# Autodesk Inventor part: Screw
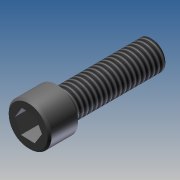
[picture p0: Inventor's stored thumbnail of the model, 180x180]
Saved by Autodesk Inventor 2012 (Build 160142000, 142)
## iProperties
Shininess: 64.0
Length Units: 11272
Angle Units: 11278
Time Units: 11290
Mass Units: 11284
Length Display Precision: 3
Angle Display Precision: 2
Compacted: True
Part Number: Screw
Document SubType Name: Modeling
Created: 2006-07
Designer: Z.MCGILL
Manufacturer: Standard
Standards Organization: Custom
Material: system_material_0
Description: SCREW, CAP, 1/4-20 X 3/8
Engineer: SAP
Density: 7.84168 g/cm^3
Mass: 26.2447 g
Surface Area: 18.9522 cm^2
Volume: 3.34682 cm^3
Density: 0.0
Volumn: 0.0
Area: 0.0
PropertySet Name: Model Information
Control State: 0
Master: False
Checked Out: False
NetWeight: 0.005
WeightUOM: KG
ModelCode: Comp
Author: Z.MCGILL
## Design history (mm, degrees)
sketch "PROTRUSION id 114-Sketch"
  geometry: L1 (0, 9.525)-(-7.144, 9.525); L2 (-7.144, 9.525)-(-7.144, 0); L3 (-7.144, 0)-(-4.763, 0); L4 (-4.763, 0)-(-4.763, -31.75); L5 (-4.763, -31.75)-(0, -31.75); L6 (0, -31.75)-(0, 9.525); L7 (0, 14.605)-(0, -27.305); L8 (0, -546.1)-(0, 3054.35) reference; L9 (0, 0)-(0, 2540); L10 (-515.143, 0)-(3049.19, 0) reference; L11 (0, 0)-(2540, 0)
  constraints: 18 end point, 2 collinear
  dimensions: "Thread_Length" = 31.75 distance between parallel lines of L3 L5; "Thread_Diameter" = 9.525 diameter of L4 L6; "Head_Diameter" = 14.2875 diameter of L2 L6; "Head_Length" = 9.525 distance between parallel lines of L1 L3
revolve "PROTRUSION id 114" sketch "PROTRUSION id 114-Sketch" stored, may be unused: angle "d6" = 0 deg
chamfer "head_chamfer" distance "Head_Chamfer" = 0.635; stored, may be unused: second distance "d8" = 0.4, angle "d9" = 2578.31 deg
chamfer "thread_chamfer" distance "Thread_Chamfer" = 0.2286; stored, may be unused: second distance "d11" = 0.5, angle "d12" = 2578.31 deg
thread "Thread1" dims "d16" = 10, "d17" = 0
sketch "Sketch5"
  geometry: L1 (2.435, 3.882)-(4.58, -0.167); L2 (4.58, -0.167)-(2.145, -4.05); L3 (2.145, -4.05)-(-2.435, -3.882); L4 (-2.435, -3.882)-(-4.58, 0.167); L5 (-4.58, 0.167)-(-2.145, 4.05); L6 (-2.145, 4.05)-(2.435, 3.882); C1 r 7.144 at (0, 0) reference; 1 further point
  constraints: 12 end point, 1 coincident, 11 other
  dimensions: "Hex_Head_Width" = 7.9375 distance between parallel lines of L3 L6
extrude "hex_depth" cut sketch "Sketch5" taper "d23" = 0 deg; distance "Hex_Head_Depth" = 7.9375
body "Solid1"
other parameters: "d24" = 0
